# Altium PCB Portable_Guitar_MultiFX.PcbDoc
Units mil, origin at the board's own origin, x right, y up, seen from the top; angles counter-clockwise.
Board outline 1525 x 3675 mil, 2 copper layers (Top Layer, Bottom Layer), stack 62.249 mil thick; 67 components, 41 nets, 234 pads, 165 vias.
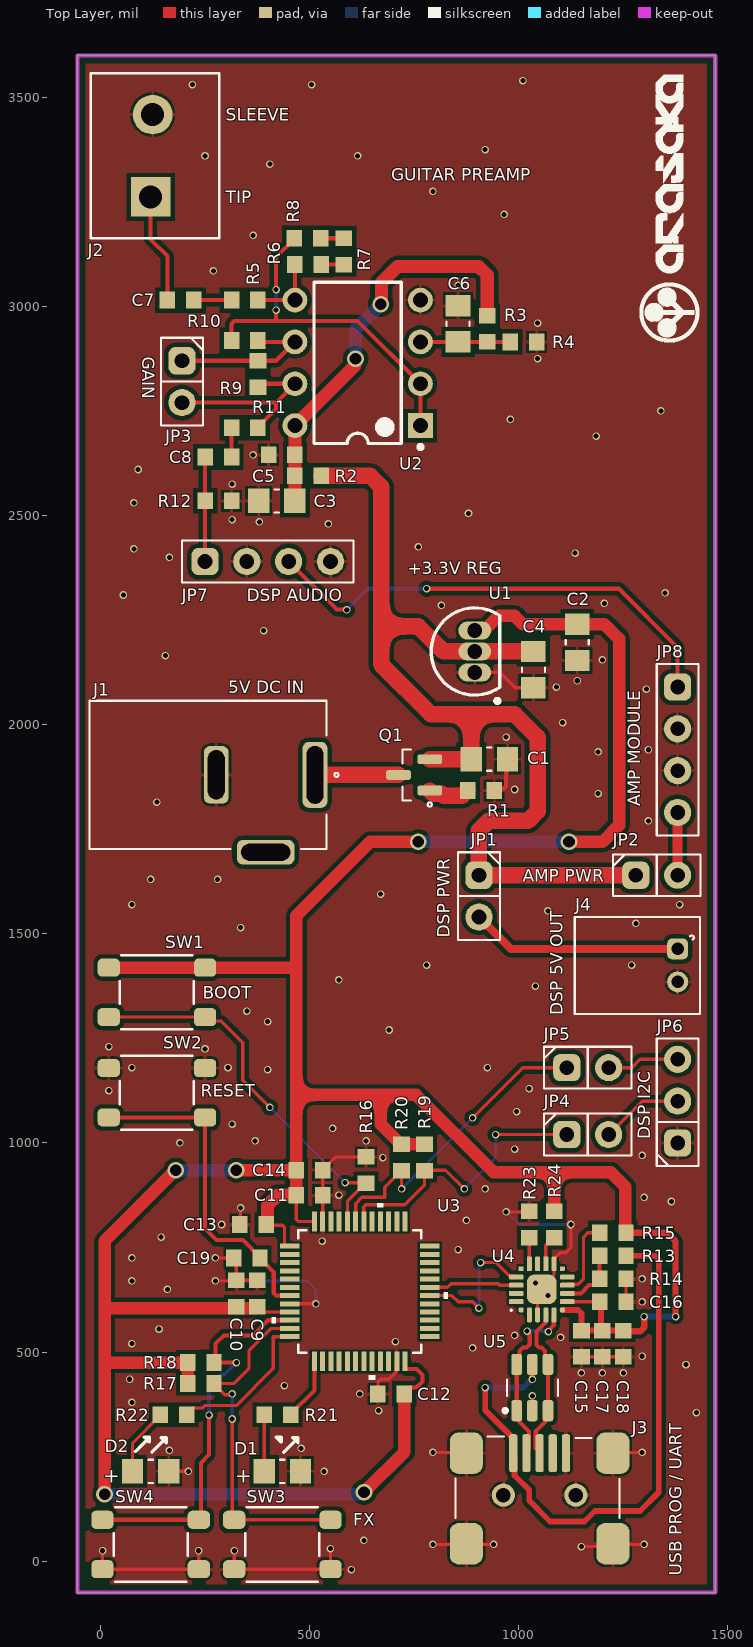
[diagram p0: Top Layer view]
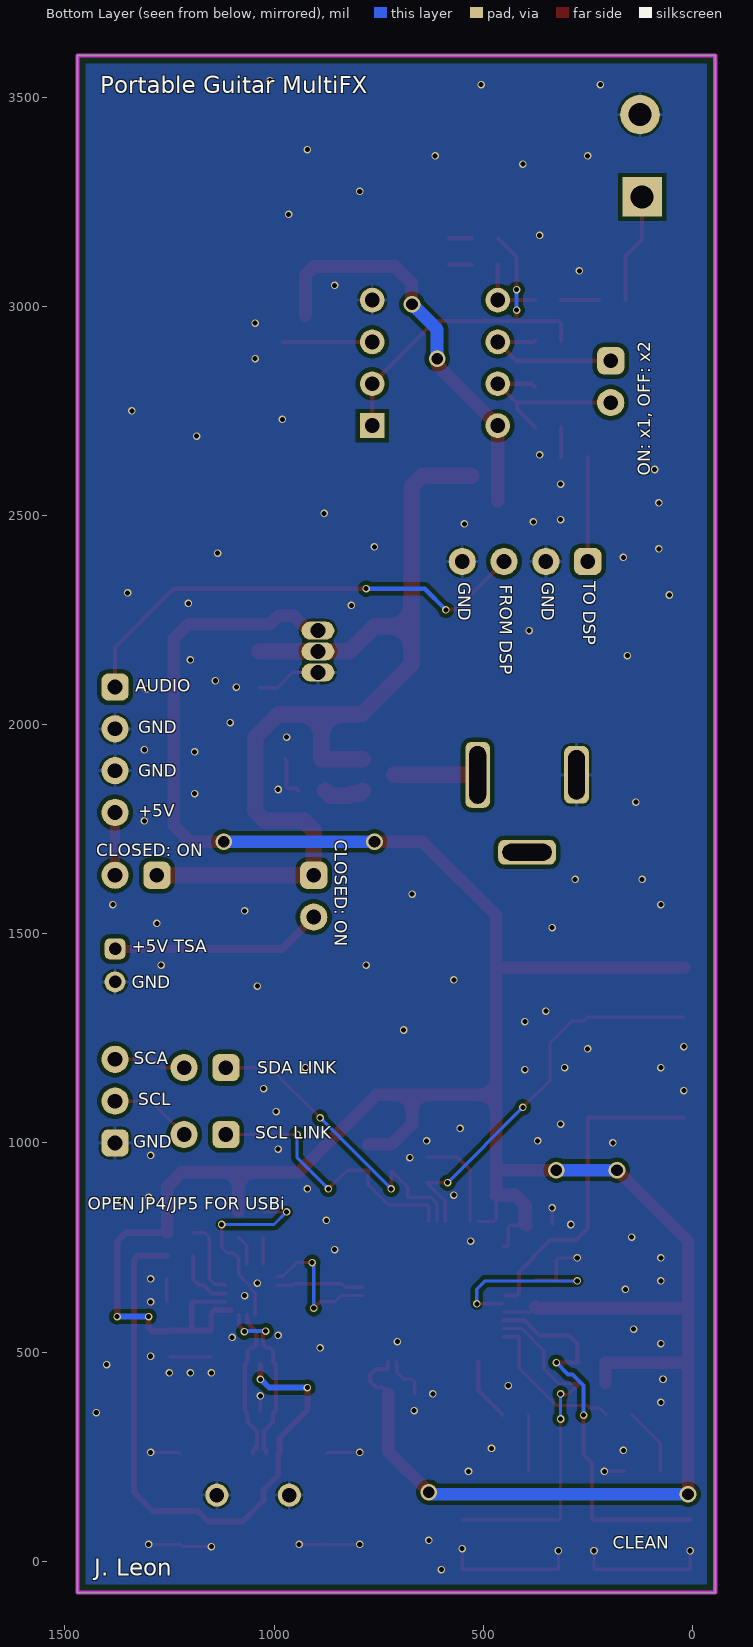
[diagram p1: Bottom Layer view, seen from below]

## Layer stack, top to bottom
Top Solder: solder mask 0.4, Solder Resist, Dk 3.5
Top Layer: signal copper 1.4
Dielectric 1: dielectric 59.4488, FR-4, Dk 4.8
Bottom Layer: signal copper 1.4
Bottom Solder: solder mask 0.4, Solder Resist, Dk 3.5

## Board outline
-55,868.75 -55,3600 1470,3600 1470,-75 -55,-75

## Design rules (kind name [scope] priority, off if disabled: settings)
BoardOutlineClearance [All] p1: gap=20 ignorepadtopadclearanceinfootprint=FALSE
Clearance Clearance_u1 [IsPad And InComponent('U1')] p1: gap=6 ignorepadtopadclearanceinfootprint=FALSE
Clearance Clearance_u4 [IsPad And InComponent('U4')] p2: gap=6 ignorepadtopadclearanceinfootprint=TRUE
Clearance Clearance_u3 [IsPad And InComponent('U3')] p3: gap=6 ignorepadtopadclearanceinfootprint=TRUE
Clearance "Clearence vias" [IsVia] p4 off: gap=8 ignorepadtopadclearanceinfootprint=TRUE
Clearance "Same Differential Pair" [InNet('USB_DP') or InNet('USB_DM') vs InNet('USB_DP') Or InNet('USB_DM')] p5: gap=6 ignorepadtopadclearanceinfootprint=FALSE
Clearance [All] p6: gap=10 ignorepadtopadclearanceinfootprint=TRUE
DiffPairsRouting [All] p1: maxlimit=6 minlimit=6 mostfreqgap=6 toplayer_minwidth=10 toplayer_maxwidth=28 toplayer_prefwidth=28 bottomlayer_minwidth=10 bottomlayer_maxwidth=28 bottomlayer_prefwidth=28 maxuncoupledlength=500
HoleSize HoleSize_J1_Ranuras [IsPad And InComponent('J1')] p1: absolutevalues=TRUE maxlimit=137.8 minlimit=1 maxpercent=80.000 minpercent=20.000
HoleSize [All] p2: absolutevalues=TRUE maxlimit=200 minlimit=12 maxpercent=80.000 minpercent=20.000
HoleToHoleClearance [All] p1: gap=12 allowstackedmicrovias=TRUE
MinimumAnnularRing [All] p1: minimumring=3
MinimumSolderMaskSliver [All] p1: minsoldermaskwidth=3.94
PolygonConnect PolygonConnect_1 [InNet('GND')] p1: thpad.connectstyle=Relief thpad.reliefconductorwidth=8 thpad.reliefentries=4 thpad.polygonreliefangle="90 Angle" thpad.airgapwidth=6 smdpad.connectstyle=Relief smdpad.reliefconductorwidth=8 smdpad.reliefentries=4 smdpad.polygonreliefangle="90 Angle" smdpad.airgapwidth=6 via.connectstyle=Direct via.reliefconductorwidth=10 via.reliefentries=4 via.polygonreliefangle="90 Angle" via.airgapwidth=10
PolygonConnect [All] p2: connectstyle=Relief reliefconductorwidth=10 reliefentries=4 polygonreliefangle="90 Angle" airgapwidth=10
RoutingVias [All] p1: holewidth=12 width=22 viastyle="Through Hole" minholewidth=12 minwidth=18 maxholewidth=30 maxwidth=40
RoutingVias 5V [All] p2: holewidth=28 width=48 viastyle="Through Hole" minholewidth=28 minwidth=48 maxholewidth=28 maxwidth=48
RoutingVias "5V_A Via" [InNet('+5V_A')] p3: holewidth=11.81 width=23.62 viastyle="Through Hole" minholewidth=11.81 minwidth=23.62 maxholewidth=11.81 maxwidth=23.62
SilkToSilkClearance [All] p1: silktosilkclearance=2
SilkToSolderMaskClearance [IsPad] p1: minsilkscreentomaskgap=0.1 clearancetoexposedcopper=TRUE
SolderMaskExpansion SolderMaskExpansion_vias [IsVia] p1: expansion=2 istentingtop=TRUE
SolderMaskExpansion [All] p2: expansion=2 istentingtop=FALSE
SupplyNets "Schematic Supply Nets_6" [InNet('+5V_A')] p1: voltage=0.000
SupplyNets "Schematic Supply Nets_5" [InNet('GND')] p2: voltage=0.000
SupplyNets "Schematic Supply Nets_4" [InNet('VIN_5V_RAW')] p3: voltage=0.000
SupplyNets "Schematic Supply Nets_3" [InNet('+5V_SYS')] p4: voltage=0.000
SupplyNets "Schematic Supply Nets_2" [InNet('+5V_AMP')] p5: voltage=0.000
SupplyNets "Schematic Supply Nets_1" [InNet('+3V3_CTRL')] p6: voltage=0.000
SupplyNets "Schematic Supply Nets" [InNet('+5V_TSA')] p7: voltage=0.000
Width W_CONTROL_Y_ANALOGICA [InNet('+3V3_CTRL') OR InNet('+5V_A')] p1: maxlimit=31.5 minlimit=7.87 preferedwidth=13.78
Width W_5V_TSA [InNet('+5V_TSA')] p2: maxlimit=39.37 minlimit=11.81 preferedwidth=19.68
Width W_5V_ENTRADA [InNet('VIN_5V_RAW') OR InNet('+5V_SYS')] p3: maxlimit=78.74 minlimit=23.62 preferedwidth=39.37
Width W_5V_AMP [InNet('+5V_AMP')] p4: maxlimit=78.74 minlimit=23.62 preferedwidth=39.37
Width W_GENERAL [All] p5: maxlimit=39.37 minlimit=7.87 preferedwidth=9.84
24 further rules are at their usual default settings.

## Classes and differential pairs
component class U_04_Interfaces_Audio: J4 JP6 JP7 JP8
component class U_03_Control: C9 C10 C11 C12 C13 C14 C15 C16 C17 C18 C19 D1 D2 J3 JP4 JP5 R13 R14 R15 R16 R17 R18 R19 R20 R21 R22 R23 R24 SW1 SW2 SW3 SW4 U3 U4 U5
component class U_02_Entrada_Guitarra: C5 C6 C7 C8 J2 JP3 R3 R4 R5 R6 R7 R8 R9 R10 R11 R12 U2
component class U_01_Alimentacion: C1 C2 C3 C4 J1 JP1 JP2 Q1 R1 R2 U1
differential pair USB: +USB_DP -USB_DM

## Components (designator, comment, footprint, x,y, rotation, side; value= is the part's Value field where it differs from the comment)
C1 "10uF 25V" 0805_cap 930,1917.4 r0 top value=10uF
C2 "10uF 25V" 0805_cap 1140,2196.69 r90 top value=10uF
C3 "22uF 16V" 0805_cap 421.69,2535 r180 top value=22uF
C4 "10uF 25V" 0805_cap 1035,2131.69 r90 top value=10uF
C5 "0.1uF 50V" 0603_cap 433.5,2645 r180 top value=0.1uF
C6 "10uF 25V" 0805_cap 855,2958.31 r90 top value=10uF
C7 "470nF 50V" 0603_cap 191.5,3015 r0 top value=470nF
C8 "1uF 50V" 0603_cap 282,2640 r180 top value=1uF
C9 "1uF 50V" 0603_cap 375,640 r90 top value=1uF
C10 "0.1uF 50V" 0603_cap 325,640 r90 top value=0.1uF
C11 "0.1uF 50V" 0603_cap 500,875 r0 top value=0.1uF
C12 "0.1uF 50V" 0603_cap 695,400 r0 top value=0.1uF
C13 "0.1uF 50V" 0603_cap 365,805 r0 top value=0.1uF
C14 "10uF 10V" 0603_cap 500,935 r0 top value=10uF
C15 "10uF 10V" 0603_cap 1150,520 r270 top value=10uF
C16 "0.1uF 50V" 0603_cap 1225,620 r0 top value=0.1uF
C17 "10uF 10V" 0603_cap 1200,520 r270 top value=10uF
C18 "0.1uF 50V" 0603_cap 1250,520 r270 top value=0.1uF
C19 "0.1uF 50V" 0603_cap 350,725 r180 top value=0.1uF
D1 "2V" 0805_LED 435,215 r0 top
D2 "2.9V" 0805_LED 120,215 r0 top
J1 "PWR JACK 2.1mm" CON_POWER_BARREL_2.1MM_3CONN 395,1880 r270 top
J2 "Connector 2pos" CON_2x1_TH_5MM 130,3360 r90 top
J3 "USB Mini B" CON_5x1_SMD_miniUSB_B 1050,150 r0 top
J4 "TSA1701 - 5V A MICRO-US" CON_2x1_TH_2MM 1380,1424.37 r270 top
JP1 "2x1" H_2x1_TH_100mil 905,1590 r270 top
JP2 "2x1" H_2x1_TH_100mil 1330,1640 r0 top
JP3 "2x1" H_2x1_TH_100mil 195,2820 r270 top
JP4 "2x1" H_2x1_TH_100mil 1165,1020 r0 top
JP5 "2x1" H_2x1_TH_100mil 1165,1180 r0 top
JP6 "TSA1701 - CONTROL I2C" H_3X1_TH_100mil 1380,1100 r90 top
JP7 "TSA1701 - AUDIO ADC0/DAC0" H_4x1_TH_2.54mm 400,2390 r0 top
JP8 "PAM8302 - AUDIO Y ALIMENTACION" H_4x1_TH_2.54mm 1380,1940 r270 top
Q1 "P CH" SOT_23_3 750,1880 r180 top
R1 "10k 1/10W" 0603_res 910,1842.6 r180 top value=10k
R2 "100R 1/10W" 0603_res 496.5,2595 r0 top value=100R
R3 "10k 1/10W" 0603_res 925,2946.5 r90 top value=10k
R4 "10k 1/10W" 0603_res 1011.5,2915 r180 top value=10k
R5 "4k7 1/10W" 0603_res 345,3015 r0 top value=4k7
R6 "390k 1/10W" 0603_res 496.5,3100 r0 top value=390k
R7 "390k 1/10W" 0603_res 581.5,3131.5 r90 top value=390k
R8 "226k 1/10W" 0603_res 495,3163 r180 top value=226k
R9 "10k 1/10W" 0603_res 376.5,2838.5 r270 top value=10k
R10 "10k 1/10W" 0603_res 345,2918.5 r0 top value=10k
R11 "100R 1/10W" 0603_res 345,2710 r180 top value=100R
R12 "226k 1/10W" 0603_res 282,2535 r180 top value=226k
R13 "33k2 1/10W" 0603_res 1225,730 r0 top value=33k2
R14 "73k2 1/10W" 0603_res 1225,675 r180 top value=73k2
R15 "1k 1/10W" 0603_res 1225,785 r180 top value=1k
R16 "10k 1/10W" 0603_res 635,935 r270 top value=10k
R17 "10k 1/10W" 0603_res 240,425 r180 top value=10k
R18 "10k 1/10W" 0603_res 240,475 r180 top value=10k
R19 "4k7 1/10W" 0603_res 775,965 r90 top value=4k7
R20 "4k7 1/10W" 0603_res 720,965 r90 top value=4k7
R21 "1k 1/10W" 0603_res 423.19,350 r180 top value=1k
R22 "1k 1/10W" 0603_res 175,350 r180 top value=1k
R23 "10k 1/10W" 0603_res 1025,805 r270 top value=10k
R24 "10k 1/10W" 0603_res 1085,805 r270 top value=10k
SW1 "Sw" Sw_PUSH_4.5x4.5x5mm 135,1360 r0 top
SW2 "Sw" Sw_PUSH_4.5x4.5x5mm 135,1120 r0 top
SW3 "Sw" Sw_PUSH_4.5x4.5x5mm 435,40 r0 top
SW4 "Sw" Sw_PUSH_4.5x4.5x5mm 120,40 r0 top
U1 "MCP1700-3302E/TO" TO-92-TO3 895,2175 r0 top
U2 "MCP6002-I/P" PDIP300-P8 615,2865 r180 top
U3 "STM32F030C8T6TR" LQFP48_7x7mm 620,645 r0 top
U4 "CP2102N-A02-GQFN20R" WFQFN_20_EP_3X3MM 1055,650 r90 top
U5 "USBLC6-2SC6" SOT_23_6 1032.6,415.12 r90 top

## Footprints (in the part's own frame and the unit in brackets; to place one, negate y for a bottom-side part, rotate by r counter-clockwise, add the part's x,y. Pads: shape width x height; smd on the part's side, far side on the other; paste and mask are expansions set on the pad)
0603_cap [mil]
  rect 37x40 smd: 1(-31.5,0) 2(31.5,0)
  body extent -31,-17 31,17, height 34
0603_res [mil] "1608 Metric / 20190225 / C-A.Serna.A"
  rect 37x40 smd: 1(-31.5,0) 2(31.5,0)
  body extent -31,-16 32,16, height 12
0805_cap [mm]
  rect 1.3x1.5 smd: 1(-1.1,0) 2(1.1,0)
  silkscreen extent -0.13,-0.7 0.13,0.7, body extent -1.13,-0.7 1.07,0.7, height 1
0805_LED [mm]
  rect 1.3x1.5 smd: 1(-1.1,0) 2(1.1,0)
  silkscreen extent -0.36,-0.7 0.95,2.07, body extent -1,-0.62 1,0.63, height 1.1
CON_2x1_TH_2MM [mil] "/20190307/N-A.Potosi"
  rrect50% 50x50 hole 30: 1(-39.37,0)
  round 50 hole 30: 2(39.37,0)
  silkscreen extent -116,-246 116,53, body extent -117,-247 116,52, height 189
CON_2x1_TH_5MM [mm]
  rect 2.4x2.4 hole 1.4: 1(-2.5,0.254)
  round 2.4 hole 1.4: 2(2.5,0.127)
  silkscreen extent -5,-3.9 5,3.9, body extent -5,-3.9 5,3.9, height 10.2
CON_5x1_SMD_miniUSB_B [mm]
  rrect50% 2x2.5 smd: 0(-4.45,-2.75) 0(-4.45,2.75) 0(4.45,-2.75) 0(4.45,2.75)
  round 1.4 hole 0.889: 0(-2.2,0.2) 0(2.2,0.2)
  rrect50% 0.5x2.3 smd: 1(-1.6,2.75) 2(-0.8,2.75) 3(0,2.75) 4(0.8,2.75) 5(1.6,2.75)
  silkscreen extent -5.11,-1.18 4.85,3.76, body extent -5.1,-5.6 4.8,3.65, height 4
CON_POWER_BARREL_2.1MM_3CONN [mm]
  rrect50% 4x1.5 hole 1.016 slot 3.5 at 0 deg: 1(0,3)
  rrect50% 3.5x1.5 hole 1.016 slot 3 at 0 deg: 2(0,-3)
  rrect50% 1.5x3.5 hole 1.016 slot 3 at 90 deg: 3(4.7,0)
  silkscreen extent -4.5,-10.7 4.5,4.43, body extent -4.5,-10.7 4.9,3.7, height 11
H_2x1_TH_100mil [mil]
  rrect50% 65x65 hole 35: 1(-50,0)
  round 65 hole 35: 2(50,0)
  silkscreen extent -105,-50 105,50, body extent -101,-49 99,49, height 339
H_3X1_TH_100mil [mil]
  rrect50% 65x65 hole 35: 1(-100,0)
  round 65 hole 35: 2(0,0) 3(100,0)
  silkscreen extent -155,-50 150,50, body extent -142,-46 142,46, height 320
H_4x1_TH_2.54mm [mil]
  rrect50% 65x65 hole 35: 1(-150,0)
  round 65 hole 35: 2(-50,0) 3(50,0) 4(150,0)
  silkscreen extent -205,-50 205,50, body extent -200,-50 205,50, height 420
LQFP48_7x7mm [mil]
  rect 47x12 smd paste+0 mask+1.8: 1(-167.32,108.27) 2(-167.32,88.58) 3(-167.32,68.9) 4(-167.32,49.21) 5(-167.32,29.53) 6(-167.32,9.84) 7(-167.32,-9.84) 8(-167.32,-29.53) 9(-167.32,-49.21) 10(-167.32,-68.9) 11(-167.32,-88.58) 12(-167.32,-108.27) 25(167.32,-108.27) 26(167.32,-88.58) 27(167.32,-68.9) 28(167.32,-49.21) 29(167.32,-29.53) 30(167.32,-9.84) 31(167.32,9.84) 32(167.32,29.53) 33(167.32,49.21) 34(167.32,68.9) 35(167.32,88.58) 36(167.32,108.27)
  rect 12x47 smd paste+0 mask+1.8: 13(-108.27,-167.32) 14(-88.58,-167.32) 15(-68.9,-167.32) 16(-49.21,-167.32) 17(-29.53,-167.32) 18(-9.84,-167.32) 19(9.84,-167.32) 20(29.53,-167.32) 21(49.21,-167.32) 22(68.9,-167.32) 23(88.58,-167.32) 24(108.27,-167.32) 37(108.27,167.32) 38(88.58,167.32) 39(68.9,167.32) 40(49.21,167.32) 41(29.53,167.32) 42(9.84,167.32) 43(-9.84,167.32) 44(-29.53,167.32) 45(-49.21,167.32) 46(-68.9,167.32) 47(-88.58,167.32) 48(-108.27,167.32)
  silkscreen extent -211,-211 211,211, body extent -177,-177 177,177, height 63
PDIP300-P8 [mm] "8-Pin Plastic Dual In-Line Package (PDIP)"
  rect 1.5x1.5 hole 0.9: 1(-3.81,3.81)
  round 1.5 hole 0.9: 2(-3.81,1.27) 3(-3.81,-1.27) 4(-3.81,-3.81) 5(3.81,-3.81) 6(3.81,-1.27) 7(3.81,1.27) 8(3.81,3.81)
  silkscreen extent -3.94,-4.9 2.65,5.23, body extent -3.55,-4.9 3.55,4.9, height 4.32
SOT_23_3 [mm]
  rrect50% 1.5x0.6 smd: 1(-0.95,0.95) 2(-0.95,-0.95) 3(0.95,0)
  silkscreen extent -1.07,-1.55 0.7,1.92, body extent -0.7,-1.52 0.7,1.53, height 1.12
SOT_23_6 [mm]
  rrect50% 1.3x0.65 smd: 1(-1.4,0.95) 2(-1.4,0) 3(-1.4,-0.95) 4(1.4,-0.95) 5(1.4,0) 6(1.4,0.95)
  silkscreen extent -1.52,-1.55 0.5,1.78, body extent -1.5,-1.45 1.3,1.45, height 1.45
Sw_PUSH_4.5x4.5x5mm [mm]
  rrect50% 1.35x1.1 smd: 1(-2.925,1.5) 1(2.925,1.5) 2(-2.925,-1.5) 2(2.925,-1.5)
  silkscreen extent -2.25,-2.25 2.25,2.25, body extent -2.25,-2.25 2.25,2.25, height 5
TO-92-TO3 [mm] "TO, Flat Index; 3 In-Line, Axial Leads; Body Dia. 4.8mm; Leads 0.56 x 0.53 mm (max)"
  oval 2x1.1 hole 0.9: 1(0,-1.27)
  oval 2x1.103 hole 0.9: 2(0,0) 3(0,1.27)
  silkscreen extent -2.65,-3.13 1.52,2.65, body extent -2.65,-2.66 1.52,2.66, height 5.33
WFQFN_20_EP_3X3MM [mm]
  rrect50% 0.3x0.3 smd: 1(-1.25,1.25) 6(-1.25,-1.25) 11(1.25,-1.25)
  rrect50% 0.9x0.3 smd: 2(-1.55,0.75) 3(-1.55,0.25) 4(-1.55,-0.25) 5(-1.55,-0.75) 12(1.55,-0.75) 13(1.55,-0.25) 14(1.55,0.25) 15(1.55,0.75)
  rrect50% 0.3x0.9 smd: 7(-0.75,-1.55) 8(-0.25,-1.55) 9(0.25,-1.55) 10(0.75,-1.55) 17(0.75,1.55) 18(0.25,1.55) 19(-0.25,1.55) 20(-0.75,1.55)
  rect 0.3x0.3 smd: 16(1.25,1.25)
  rrect50% 1.8x1.8 smd: 21(0,0)
  silkscreen extent -1.32,1.8 -1.22,1.9, body extent -1.5,-1.5 1.5,1.5, height 0.8

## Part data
C1 C2 C4 C6: library part Cap_10uF_0805_25V_, "25V 10uF X5R ±10% 0805 Multilayer Ceramic Capacitors MLCC - SMD/SMT ROHS", Manufacturer="Samsung Electro-Mechanics", Manufacturer Part Number=CL21A106KAYNNNE, Supplier Part Number 1=C15850
C3: library part Cap_22uF_0805_16V, "16V 22uF X5R ±20% 0805 Multilayer Ceramic Capacitors MLCC - SMD/SMT ROHS", Manufacturer=Chinocera, Manufacturer Part Number=HGC0805R5226M160NSLJ, Supplier Part Number 1=C33546008
C5 C10 C11 C12 C13 C16 C18 C19: library part Cap_0.1uF_0603_50V, "50V 100nF Y5V -20%~+80% 0603 Multilayer Ceramic Capacitors MLCC - SMD/SMT ROHS", Manufacturer="Walsin Tech Corp", Manufacturer Part Number=0603F104Z500CT, Supplier Part Number 1=C83060
C7: library part Cap_470nF_0603_50V, "50V 470nF X7R ±10% 0603 Multilayer Ceramic Capacitors MLCC - SMD/SMT ROHS", Manufacturer=Chinocera, Manufacturer Part Number=HGC0603R7474K500NTHJ, Supplier Part Number 1=C33546006
C8 C9: library part Cap_1uF_0603_50V, "50V 1uF X5R ±10% 0603 Multilayer Ceramic Capacitors MLCC - SMD/SMT ROHS", Manufacturer="Samsung Electro-Mechanics", Manufacturer Part Number=CL10A105KB8NNNC, Supplier Part Number 1=C15849
C14 C15 C17: library part Cap_10uF_0603_10V, "10V 10uF X5R ±10% 0603 Multilayer Ceramic Capacitors MLCC - SMD/SMT ROHS", Manufacturer=CCTC, Manufacturer Part Number=TCC0603X5R106K100CT, Supplier Part Number 1=C380314
D1: library part LED_0805_RED, "LED RED CLEAR 0805 SMD", Manufacturer=XINGLIGHT, Manufacturer Part Number=XL-2012SURC, Supplier Part Number 1=C965812
D2: library part LED_0805_Green, "LED GREEN CLEAR 0805 SMD", Manufacturer=XINGLIGHT, Manufacturer Part Number=XL-2012UGC, Supplier Part Number 1=C965815
J1: library part Con_Power_Jack_2.1mm_3pins, "CONN PWR JACK 2X5.5MM SOLDER", Manufacturer=HCTL, Manufacturer Part Number=HC-DC-005-2.0T, Supplier Part Number 1=C3010533
J2: library part Con_2x1_TH_5mm, "2POS 5MM", Manufacturer=JILN, Manufacturer Part Number=JL126-50002G01, Supplier Part Number 1=C394556
J3: library part Con_Mini_USB_B, "CONN RCPT USB2.0 MINI B SMD R/A", Manufacturer="EDAC Inc.", Manufacturer Part Number=KH-MINI-SMT-5P-Cu, Supplier Part Number 1=C2688795
J4: library part Con_2x1_TH_JST_2MM, "2POS 2MM", Manufacturer=JST, Manufacturer Part Number=S2B-PH-K-S(LF)(SN), Supplier Part Number 1=C173752
JP1 JP2 JP3 JP4 JP5: library part H_Male_2x1_TH_100mil, "H_Male_2x1_TH_100mil"
JP6: library part H_Male_3x1_TH_100mil, "H_Male_3x1_TH_100mil"
JP7 JP8: library part H_Male_4x1_TH_100mil, "H_Male_4x1_TH_100mil"
Q1: library part Q_PFET_30V_3A_SOT23, "MOSFET P-CH 20V 3A SOT23", Manufacturer="ALLPOWER(ShenZhen Quan Li Semiconductor)", Manufacturer Part Number=AP2301, Supplier Part Number 1=C385296
R1 R3 R4 R9 R10 R16 R17 R18 R23 R24: library part Res_10k_0603_1/10W, "RES SMD 10k OHM 5% 1/10W 0603", Manufacturer=FOJAN, Manufacturer Part Number=FRC0603J103TS, Supplier Part Number 1=C2930027
R2 R11: library part Res_100R_0603_1/10W, "RES SMD 100R OHM 5% 1/10W 0603", Manufacturer=FOJAN, Manufacturer Part Number="FRC0603J101 TS", Supplier Part Number 1=C2907089
R5 R19 R20: library part Res_4k7_0603_1/10W, "100mW Thick Film Resistor 75V ±1% 4.7kΩ 0603 Chip Resistor - Surface Mount ROHS", Manufacturer=VO, Manufacturer Part Number=SCR0603F4K7, Supplier Part Number 1=C3016318
R6 R7: library part Res_390k_0603_1/10W, "100mW Thick Film Resistor 75V ±100ppm/℃ ±1% 390kΩ 0603 Chip Resistor - Surface Mount ROHS", Manufacturer=YAGEO, Manufacturer Part Number=RC0603FR-07390KL, Supplier Part Number 1=C137735
R8 R12: library part Res_226k_0603_1/10W, "100mW Thick Film Resistors 75V ±100ppm/℃ ±1% 226kΩ 0603 Chip Resistor - Surface Mount ROHS", Manufacturer=YAGEO, Manufacturer Part Number=RC0603FR-07226KL, Supplier Part Number 1=C165744
R13: library part Res_33k2_0603_1/10W, "100mW Thick Film Resistor 75V ±100ppm/℃ ±1% 33.2kΩ 0603 Chip Resistor - Surface Mount ROHS", Manufacturer=YAGEO, Manufacturer Part Number=RC0603FR-0733K2L, Supplier Part Number 1=C185338
R14: library part Res_73k2_0603_1/10W, "100mW Thick Film Resistor 75V ±100ppm/℃ ±1% 73.2kΩ 0603 Chip Resistor - Surface Mount ROHS", Manufacturer=YAGEO, Manufacturer Part Number=RC0603FR-0773K2L, Supplier Part Number 1=C163420
R15 R21 R22: library part Res_1k_0603_1/10W, "RES SMD 1k OHM 5% 1/10W 0603", Manufacturer=FOJAN, Manufacturer Part Number="FRC0603J102 TS", Supplier Part Number 1=C2907113
SW1 SW2 SW3 SW4: library part Sw_PUSH_4.5x4.5x5.0xmm, "SWITCH TACTILE SPST-NO 0.05A 12V", Manufacturer=BZCN, Manufacturer Part Number=TSC015A05026A, Supplier Part Number 1=C2888509
U1: library part CMP-0136-00007-1, "Low Quiescent Current LDO, 3-Pin TO-92, Extended TemperatureBAG"
U2: library part CMP-0187-00119-3, "None", Case/Package=PDIP, Input Bias Current=1pA, Input Offset Voltage (Vos)=4.5mV, Max Frequency=1kHz, Max Input Voltage=6V, Max Operating Temperature=85°C, Min Input Voltage=1.8V, Min Operating Temperature=-40°C, Nominal Supply Current=100uA, Operating Supply Voltage=5.5V, Output Current=23mA, Package Quantity=60, Power Supply Rejection Ratio (PSRR)=86dB, Voltage Gain=112dB
U3: library part IC_STM32F030C8T6TR_LQFP48_7x7MM, "IC MCU 32BIT 64KB FLASH 48LQFP", Manufacturer=STMicroelectronics, Supplier Part Number 1=C23922
U4: library part IC_SGL_USB2UART-BRIDGE_20QFN, "IC USB TO UART BRIDGE QFN20", Manufacturer="Silicon Labs", Supplier Part Number 1=C969913
U5: library part TVS_5.25V_2CH_SOT_23_6, "TVS DIODE 5.25V 17V SOT23-6", Manufacturer=STMicroelectronics, Supplier Part Number 1=C7519

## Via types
v1: diameter 18, hole 12, Top Layer to Bottom Layer, tented both sides, 157 vias
v2: diameter 40, hole 28, Top Layer to Bottom Layer, tented both sides, 8 vias

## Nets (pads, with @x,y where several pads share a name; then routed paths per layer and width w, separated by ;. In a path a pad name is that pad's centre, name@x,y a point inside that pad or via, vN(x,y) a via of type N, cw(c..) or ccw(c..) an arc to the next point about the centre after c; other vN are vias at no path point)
+3V3_CTRL: C2.2 C9.1 C10.1 C11.1 C12.2 C13.2 C14.1 C15.1 C16.1 C17.1 C18.1 R15.1 R17.2 R18.2 R19.2 R20.2 R24.1 SW1.1 U1.3 U3.1 U3.9 U3.24 U3.48 U4.6 U4.7 | length 8083.2
  Top Layer w7.87: C9.1 387.71,595.79 U3.9 ; C13.2@396.5,803.5 435.39,803.5 440,798.89 440,755.33 442.06,753.27 U3.1 ; C11.1 468.5,816.94 473.11,812.32 U3.48 ; U4.7 1116.18,620.32 1193.18,620.32 C16.1
  Top Layer w10: C12.2 726.5,401.5 740,415 755,415 770,430 770,445 755.82,459.18 729.27,459.18 728.27,460.18 U3.24
  Top Layer w13.78: U4.6 1141.93,600.79 1150,592.72 C15.1 C17.1 ; C16.1 1196.75,616.75 1196.75,554.75 C17.1 ; C18.1 C17.1
  Top Layer w15: C18.1 1251.5,550 1291.21,550 1300,558.79 v1(1300,585) ; R15.1 1355,785 1375,765 v1(1375,585)
  Top Layer w30: v2(10,160) 10,475 ; SW1.1@19.84,1419.06 250.16,1419.06 468.5,1419.06 ; v2(180,935) 10,765 10,605 ; R17.2 R18.2 10,475 ; v2(325,935) C14.1 ; C9.1 371.5,605 10,605 ; C11.1@468.5,875.28 C14.1 ; v2(630,165) 726.5,261.5 C12.2 ; v2(760,1720) 645,1720 468.5,1543.5 468.5,1419.06 ; R19.2 R20.2 718.5,996.5 670,1045 670,1115 ; U1.3 917.22,2225 952.22,2260 990,2260 1010,2240 C2.2 1205,2240 1214.99,2230.01 1240,2205 1240,1760 1200,1720 v2(1120.13,1720) ; R24.1 1085,930 ; R15.1 1255,786.5 1255,895 1220,930 1085,930 ; 10,475 10,605 ; C14.1 468.5,1115 ; 468.5,1115 468.5,1419.06 ; 468.5,1115 670,1115 ; 670,1115 755,1115 940,930 1085,930
  Top Layer w31.5: C13.2@396.5,803.5 399.25,806.25 399.25,850.8 423.45,875 C11.1
  Bottom Layer w15: v1(1300,585) v1(1375,585)
  Bottom Layer w30: v2(10,160) 622.29,160 627.29,165 v2(630,165) ; v2(180,935) v2(325,935) ; v2(760,1720) v2(1120.13,1720)
+5V_A: C3.1 C5.1 R2.1 R3.2 U2.8 | length 981.8
  Top Layer w31.5: C3.1 R2.1 C5.1 U2.8 608.37,2858.37 608.37,2873.37 v2(610,2875) ; v2(670,3005) 671.63,3006.63 671.63,3056.63 710,3095 905,3095 925,3075 R3.2
  Bottom Layer w31.5: v2(610,2875) 610,2945 v2(670,3005)
+5V_AMP: JP2.2 JP8.4 | length 150
  Top Layer w23.62: JP2.2 JP8.4
+5V_SYS: C1.1 C4.2 JP1.1 JP2.1 Q1.2 R2.2 U1.2 | length 2438.8
  Top Layer w39.37: R2.2 645,2595 671.06,2568.94 671.06,2235 ; Q1.2 C1.1 886.69,2025 ; U1.2 820,2175 760,2235 671.06,2235 ; U1.2@895,2175.63 1034.37,2175.63 C4.2 ; JP2.1 JP1.1 905,1746.94 928.06,1770 1021.94,1770 1045,1793.06 1045,1970 990,2025 886.69,2025 ; 671.06,2235 671.06,2143.94 790,2025 886.69,2025
+5V_TSA: J4.1 JP1.2 | length 506.6
  Top Layer w19.68: JP1.2 981.26,1463.74 J4.1
BOOT: R16.2 SW1.2 U3.44 | length 943
  Top Layer w7.87: SW1.2@19.84,1300.94 250.16,1300.94 259.65,1291.46 288.54,1291.46 340,1240 340,1150 v1(405,1085) ; v1(585,905) 633.5,905 R16.2 633.5,903.5 590.47,860.47 U3.44
  Bottom Layer w7.87: v1(405,1085) v1(585,905)
BTN_CLEAN: R18.1 SW4.1 U3.10 | length 950.2
  Top Layer w9.84: SW4.1@4.84,99.06 235.16,99.06 240,103.9 240,235 260,255 v1(260,349.13) ; v1(325,475) 275,475 R18.1 275,478.5 275,520 295,540 365,540 401.1,576.1 U3.10
  Bottom Layer w9.84: v1(260,349.13) 260,420 286.72,446.72 296.72,446.72 v1(325,475)
BTN_FX: R17.1 SW3.1 U3.11 | length 850.8
  Top Layer w7.87: v1(315,340) 315,103.9 319.84,99.06 SW3.1@550.16,99.06 ; v1(315,400) 312.26,400 310.06,397.8 297.2,397.8 271.5,423.5 R17.1 320,425 355,460 355,503.33 408.09,556.42 U3.11
  Bottom Layer w7.87: v1(315,340) v1(315,400)
DSP_LINE_OUT: JP7.3 JP8.1 | length 1152
  Top Layer w9.84: JP7.3 565.13,2274.87 588.26,2274.87 v1(588.89,2274.24) ; v1(780,2325) 1240,2325 1380,2185 JP8.1
  Bottom Layer w9.84: v1(588.89,2274.24) 639.66,2325 v1(780,2325)
GND: C1.2 C2.1 C3.2 C4.1 C5.2 C6.2 C9.2 C10.2 C11.2 C12.1 C13.1 C14.2 C15.2 C16.2 C17.2 C18.2 C19.2 D1.2 D2.2 J1.2 J2.2 J3.0 J3.5 J4.2 JP6.1 JP7.2 JP7.4 JP8.2 JP8.3 R1.1 R4.1 R12.1 R14.1 R16.1 R23.1 SW2.1 SW3.2 SW4.2 U1.1 U2.4 U3.8 U3.23 U3.47 U4.3 U4.12 U4.21 U5.2 | length 2998.5
  Top Layer w7.87: v1(5,25) 5,-18.9 4.84,-19.06 235.16,-19.06 235,-18.9 v1(235,25) ; D2.2 v1(210,215) ; v1(275,670) 323.5,670 C10.2 ; v1(275,725) C19.2 325,718.5 C10.2 ; v1(320,25) 320,-18.9 319.84,-19.06 550.16,-19.06 550,-18.9 v1(550,30) ; C13.1 335,806.5 v1(335,845) ; C9.2 C10.2 ; U3.8 452.91,615.24 514.76,615.24 v1(515,615) ; U3.47 531.42,934.92 C14.2 531.5,936.5 546.06,951.06 547.56,951.06 563,966.5 R16.1 ; C12.1 663.5,428.5 670,435 689.77,435 706.52,451.75 706.52,475.61 U3.23 ; v1(795,40) 873.07,40 874.8,41.73 876.54,40 v1(940,40) ; v1(795,260) 873.07,260 J3.0@874.8,258.27 ; U1.1 955,2125 991.61,2088.39 C4.1 ; v1(970,835) 1023.5,835 R23.1 ; U5.2 v1(1032.6,395.43) ; U4.3 1045.16,640.16 U4.21 1055,655.69 1084.37,685.06 1084.37,710.87 U4.12 1084.53,722.83 1099.09,737.4 1112.4,737.4 1125,750 v1(1125,805) ; v1(1150,35) 1218.46,35 1225.2,41.73 1226.93,40 v1(1300,40) ; C15.2 C18.2 ; J3.0@1225.2,258.27 1226.93,260 v1(1295,260) ; C16.2 R14.1
  Top Layer w9.84: R1.1 946.5,1847.6 964.23,1847.6 970,1853.36 970,1914.1 C1.2
  Bottom Layer w7.87: v1(275,670) 495,670 515,650 v1(515,615) ; v1(970,835) 1000,805 v1(1125,805)
  other v1: 600,-20 630,50 535,215 165,265 480,270 1425,355 665,360 75,380 620,400 440,420 70,435 1150,450 1200,450 1250,450 1400,470 1295,490 890,510 75,520 705,525 1100,535 990,540 140,555 1295,620 1070,635 160,650 1040,665 75,670 1295,675 75,725 855,745 530,765 145,775 290,805 875,815 1365,860 1300,870 570,875 920,890 675,965 1295,970 990,985 190,1000 370,1005 635,1005 555,1035 315,1045 995,1075 20,1125 1025,1130 400,1175 75,1180 305,1180 925,1180 250,1225 20,1230 690,1270 400,1290 350,1315 1040,1375 570,1390 780,1425 1270,1425 335,1515 1280,1525 1070,1555 75,1570 1385,1570 670,1595 120,1630 280,1630 1310,1770 135,1815 1190,1835 990,1845 1190,1935 1310,1940 970,1970 1105,2005 1305,2085 1090,2090 1140,2105 1200,2155 155,2165 390,2225 815,2285 1205,2290 55,2310 1350,2315 165,2400 1135,2410 80,2420 760,2425 545,2480 380,2485 315,2490 880,2505 80,2530 315,2575 90,2610 365,2645 1185,2690 980,2730 1340,2750 1045,2875 1045,2960 855,3050 270,3085 365,3170 965,3220 795,3275 405,3340 250,3360 615,3360 920,3375 220,3530 505,3530 1010,3540
GTR_BIASED: R5.2 R6.1 U2.5 | length 173.5
  Top Layer w9.84: R5.2 U2.5 R6.1
LED_CLEAN: R22.1 U3.12 | length 368.6
  Top Layer w7.87: R22.1 206.5,351.5 221.06,366.06 243.63,366.06 249.63,372.06 324.5,372.06 413.43,460.99 413.43,536.48 452.43,536.48 U3.12
LED_FX: R21.1 U3.13 | length 151.3
  Top Layer w9.84: R21.1 454.69,351.5 511.73,408.54 U3.13
MCU_SCL: JP4.1 R19.1 U3.42 | length 680.9
  Top Layer w7.87: U3.42 629.84,847.51 634.45,852.13 727.13,852.13 775,900 R19.1 776.5,935 825,935 v1(870,890) ; v1(945,1020) JP4.1
  Bottom Layer w7.87: v1(870,890) 945,965 v1(945,1020)
MCU_SDA: JP5.1 R20.1 U3.43 | length 758.2
  Top Layer w7.87: U3.43 610.16,854.88 625.28,870 680,870 680,893.5 703.94,917.44 703.94,918.94 718.5,933.5 R20.1 v1(720,890) ; v1(890,1060) 1010,1180 JP5.1
  Bottom Layer w7.87: v1(720,890) v1(890,1060)
NetC6_1: C6.1 R3.1 R4.2 U2.3 | length 215
  Top Layer w9.84: U2.3 R4.2
NetC7_1: C7.1 J2.1 | length 263.1
  Top Layer w9.84: J2.1 120,3160 160,3120 C7.1
NetC7_2: C7.2 R5.1 | length 90.5
  Top Layer w9.84: C7.2 R5.1
NetC8_1: C8.1 R11.2 | length 70
  Top Layer w9.84: C8.1 R11.2
NetC8_2: C8.2 JP7.1 R12.2 | length 250.2
  Top Layer w9.84: JP7.1 250,2639.5 C8.2
NetD1_1: D1.1 R21.2 | length 135
  Top Layer w7.87: D1.1 R21.2
NetD2_1: D2.1 R22.2 | length 162.7
  Top Layer w7.87: D2.1 76.69,281.69 143.5,348.5 R22.2
NetJP3_1: JP3.1 R9.1 R10.2 U2.6 | length 378.6
  Top Layer w9.84: JP3.1 R9.1 420,2870 U2.6 380,2915 R10.2
NetJP3_2: JP3.2 R9.2 R11.1 U2.7 | length 458.2
  Top Layer w9.84: JP3.2 419,2770 419.5,2769.5 ; R11.1 376.5,2711.5 419.5,2754.5 419.5,2769.5 ; R9.2 384.5,2815 U2.7 419.5,2769.5
NetJP4_2: JP4.2 JP6.2 | length 198.1
  Top Layer w7.87: JP4.2 1295,1100 JP6.2
NetJP5_2: JP5.2 JP6.3 | length 173.3
  Top Layer w7.87: JP5.2 1270,1180 1290,1200 JP6.3
NetQ1_1: Q1.1 R1.2 | length 101.5
  Top Layer w39.37: Q1.1 795.28,1834.72 816.45,1834.72 821.18,1830 865.03,1830 877.63,1842.6 R1.2
NetR6_2: R6.2 R7.1 | length 53.5
  Top Layer w9.84: R6.2 R7.1
NetR7_2: R7.2 R8.1 | length 55
  Top Layer w9.84: R8.1 R7.2
NetR15_2: R15.2 U4.9 | length 187.9
  Top Layer w7.87: U4.9 1117.99,661.81 1141.81,661.81 1155,675 1155,775 1165,785 R15.2
NetR23_2: R23.2 U4.15 | length 62.7
  Top Layer w7.87: R23.2 1025.47,773.03 U4.15
NetR24_2: R24.2 U4.13 | length 71.7
  Top Layer w7.87: U4.13 1064.84,754.84 1083.5,773.5 R24.2
RESET: C19.1 SW2.2 U3.7 | length 789.1
  Top Layer w9.84: SW2.2@19.84,1060.94 250.16,1060.94 250,1060.79 250,795 277.46,767.54 340.46,767.54 381.5,726.5 C19.1 ; C19.1@381.5,723.5 395.08,709.92 396.18,709.92 414.26,691.85 414.26,640.77 420.02,635 446.1,635 U3.7@446.26,635.16
STM_RX: U3.31 U4.18 | length 211.9
  Top Layer w7.87: U3.31 829.75,654.84 838.53,663.62 951.38,663.62 955,660 993.82,660 U4.18
STM_TX: U3.30 U4.17 | length 340.2
  Top Layer w7.87: U3.30 839.84,635.16 855,620 890,620 v1(905,605) ; v1(908.78,714) 946,714 978.5,681.5 992.01,681.5 U4.17
  Bottom Layer w7.87: v1(905,605) 905,707.48 908.78,711.26 v1(908.78,714)
USB_5V_PC: J3.1 R13.2 U5.5 | length 1468.2
  Top Layer w13.78: v1(920,415) 920,360.71 987.01,293.7 J3.1 989.96,255.32 989.96,205.04 1025,170 1025,145 1075,95 1157.5,95 1182.5,120 1290,120 1335,165 1335,721.93 1326.93,730 R13.2 ; v1(1032.6,434.8) U5.5
  Bottom Layer w13.78: v1(920,415) 1011.65,415 1031.46,434.8 v1(1032.6,434.8)
USB_DM: J3.2 U4.5 U5.1 U5.6 | length 424.6
  Top Layer w10: J3.2 1018.5,265.16 1023.35,270 1024.6,270 1024.6,310 1002.13,332.47 1002.13,353.07 U5.1 U5.6 1002.13,477.17 1002.13,502.53 1010.43,510.83 1018.74,510.83 1026.54,518.62 1026.54,541.3 1020,547.84 v1(1020,550) ; v1(1070.96,549.04) 1070.96,551.21 1083.62,563.87 1083.62,588.07 U4.5
  Bottom Layer w10: v1(1020,550) 1070,550 v1(1070.96,549.04)
USB_DP: J3.3 U4.4 U5.3 U5.4 | length 373.7
  Top Layer w10: J3.3 1050,265.16 1045.16,270 1040.6,270 1040.6,310 1063.07,332.47 1063.07,353.07 U5.3 U5.4 1063.07,477.17 1063.07,502.53 1054.77,510.83 1048.39,510.83 1042.54,516.68 1042.54,548.91 1063.94,570.31 1063.94,576.26 1064.95,577.27 U4.4@1064.95,588.87
USB_VBUS_SENSE: R13.1 R14.2 U4.8 | length 147.8
  Top Layer w9.84: U4.8 1148.5,640.16 1168.27,659.92 1179.92,659.92 1193.5,673.5 R13.1
VIN_5V_RAW: J1.1 Q1.3 | length 199.5
  Top Layer w39.37: J1.1 Q1.3
VREF_AUDIO: R8.2 R10.1 U2.1 U2.2 | length 872.3
  Top Layer w9.84: R10.1 313.5,2958.5 320,2965 420,2965 ; v1(420,2991.08) 420,2965 ; v1(420,3040) 420,3118 463.5,3161.5 R8.2 ; U2.1 U2.2 615,2965 420,2965
  Bottom Layer w9.84: v1(420,2991.08) v1(420,3040)
pads on no net: J1.3 J3.4 U3.2 U3.3 U3.4 U3.5 U3.6 U3.14 U3.15 U3.16 U3.17 U3.18 U3.19 U3.20 U3.21 U3.22 U3.25 U3.26 U3.27 U3.28 U3.29 U3.32 U3.33 U3.34 U3.35 U3.36 U3.37 U3.38 U3.39 U3.40 U3.41 U3.45 U3.46 U4.1 U4.2 U4.10 U4.11 U4.14 U4.16 U4.19 U4.20

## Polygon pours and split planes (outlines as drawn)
GND on Top Layer "GND_TOP" (solid, remove dead copper, pour order 2): -55,-75 -55,3600 1470,3600 1470,-75
GND on Bottom Layer "GND_BOTTOM" (solid, remove dead copper, pour order 3): -55,-75 -55,3600 1470,3600 1470,-75

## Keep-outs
Keep-Out Layer:
  lines w10: -55,-75 337.5,-75 1072.5,-75 1470,-75 1470,3600 -30,3600 -55,3600 -55,2656.25 -55,868.75 -55,-75

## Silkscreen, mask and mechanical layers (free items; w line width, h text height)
Top Overlay:
  drawing of 9 lines, arcs and shapes, not listed
  text "SLEEVE" at 300,3443.43 h30
  text "GUITAR PREAMP" at 695,3300 h30
  text "TIP" at 300,3246.58 h30
  text "GAIN" at 100,2880 h30 r270
  text "+3.3V REG" at 735,2360 h30
  text "DSP AUDIO" at 350,2295 h30
  text "5V DC IN" at 305,2075 h30
  text "AMP MODULE" at 1290,1805 h30 r90
  text "AMP PWR" at 1010,1625 h30
  text "DSP PWR" at 835,1490 h30 r90
  text "BOOT" at 245,1345 h30
  text "DSP 5V OUT" at 1105,1305 h30 r90
  text "RESET" at 240,1110 h30
  text "DSP I2C" at 1315,1009.21 h30 r90
  text "FX" at 605,85 h30
  text "USB PROG / UART" at 1390,-35 h30 r90
Bottom Overlay:
  text "Portable Guitar MultiFX" at 1415,3510 h40
  text "ON: x1, OFF: x2" at 100,2595 h30 r270
  text "TO DSP" at 261.25,2342.27 h30 r90
  text "GND" at 360,2340 h30 r90
  text "GND" at 560,2340 h30 r90
  text "FROM DSP" at 460,2335 h30 r90
  text "AUDIO" at 1332.27,2078.75 h30
  text "GND" at 1325,1980 h30
  text "GND" at 1325,1875 h30
  text "+5V" at 1325,1780 h30
  text "CLOSED: ON" at 855,1725 h30 r90
  text "CLOSED: ON" at 1425,1685 h30
  text "+5V TSA" at 1339.56,1456.24 h30
  text "GND" at 1340,1370 h30
  text "SCA" at 1335.4,1188.6 h30
  text "SDA LINK" at 1040,1165 h30
  text "SCL" at 1325,1090 h30
  text "SCL LINK" at 1045,1010 h30
  text "GND" at 1336.06,988.75 h30
  text "OPEN JP4/JP5 FOR USBi" at 1445,840 h30
  text "CLEAN" at 190,30 h30
  text "J. Leon" at 1430,-35 h40
Board Shape:
  lines w10: -170,-20 -150,-80 ; -170,3535 -150,3595 ; -160,-80 -140,-80 ; -160,3595 -140,3595 ; -150,1476.59 -150,-80 ; -150,2038.41 -150,3595 ; -130,-20 -150,-80 ; -130,3535 -150,3595 ; -55,-75 -55,868.75 -55,2656.25 -55,3600 -30,3600 1470,3600 1470,-75 1072.5,-75 337.5,-75 -55,-75
  text "3675 (mil)" at -185.99,2028.41 h60 r270

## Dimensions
-55,3600 to 1470,3600 on Board Shape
